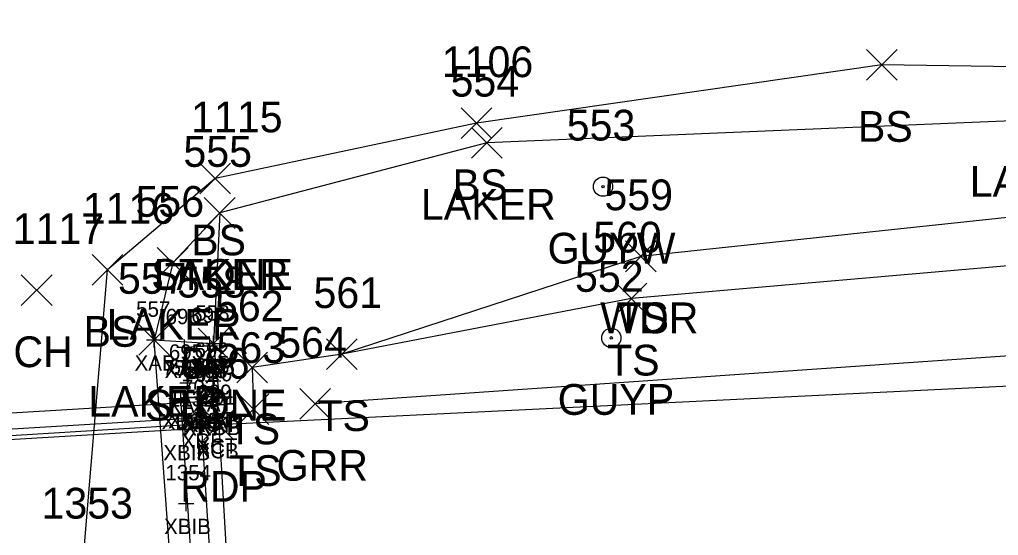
# Model space of a CAD drawing. Extents: x 1716490 to 1717645, y 888034 to 890004.
# Drawn here: x 1717164.1 to 1717227.8, y 888253.5 to 888287.1 of the extents above; entities that cross this region are included whole.
import ezdxf

# ---------------------------------------------------------------- set-up
doc = ezdxf.new("R2010")
doc.units = 0
for name, color, linetype in [('B_A', 7, 'Continuous'), ('B_I', 7, 'Continuous'), ('B_TIC', 7, 'Continuous'), ('BDC', 7, 'Continuous'), ('BF', 7, 'Continuous'), ('BR', 7, 'Continuous'), ('BSE', 7, 'Continuous'), ('BSUBM', 7, 'Continuous'), ('L_A', 7, 'Continuous'), ('L_I', 7, 'Continuous'), ('L_TIC', 7, 'Continuous'), ('LASF', 7, 'Continuous'), ('LAWA', 7, 'Continuous'), ('LAWE', 7, 'Continuous'), ('LELB', 7, 'Continuous'), ('P_A', 7, 'Continuous'), ('P_I', 7, 'Continuous'), ('P_TIC', 7, 'Continuous'), ('PET', 7, 'Continuous'), ('R_A', 7, 'Continuous'), ('R_I', 7, 'Continuous'), ('R_TIC', 7, 'Continuous'), ('RGR', 7, 'Continuous'), ('U_A', 7, 'Continuous'), ('U_I', 7, 'Continuous'), ('UPGW', 7, 'Continuous')]:
    doc.layers.add(name, color=color, linetype=linetype)

msp = doc.modelspace()

# ---------------------------------------------------------------- linework, layer by layer
at = {"layer": 'B_TIC'}
for p, q in [((1717172.863, 888266.22), (1717172.939, 888266.22)), ((1717176.717, 888265.975), (1717176.792, 888265.975)), ((1717174.834, 888265.741), (1717174.91, 888265.741)), ((1717176.473, 888265.837), (1717176.548, 888265.837)), ((1717175.018, 888263.43), (1717175.094, 888263.43)), ((1717176.687, 888263.555), (1717176.762, 888263.555)), ((1717174.599, 888262.408), (1717174.675, 888262.408)), ((1717175.062, 888262.468), (1717175.137, 888262.468)), ((1717175.803, 888262.49), (1717175.879, 888262.49)), ((1717176.593, 888262.234), (1717176.668, 888262.234)), ((1717176.593, 888262.234), (1717176.668, 888262.234)), ((1717176.726, 888262.528), (1717176.802, 888262.528)), ((1717177.084, 888262.456), (1717177.16, 888262.456)), ((1717176.001, 888261.982), (1717176.076, 888261.982)), ((1717176.979, 888262.024), (1717177.055, 888262.024)), ((1717175.884, 888261.141), (1717175.959, 888261.141)), ((1717176.881, 888260.812), (1717176.956, 888260.812)), ((1717174.882, 888260.387), (1717174.958, 888260.387)), ((1717176.87, 888260.514), (1717176.945, 888260.514)), ((1717174.931, 888255.588), (1717175.006, 888255.588))]:
    msp.add_line(p, q, dxfattribs=at)
for points in [[(1717172.86, 888265.72), (1717172.86, 888266.72)], [(1717172.36, 888266.22), (1717173.36, 888266.22)], [(1717174.831, 888265.241), (1717174.831, 888266.241)], [(1717176.213, 888265.975), (1717177.213, 888265.975)], [(1717176.469, 888265.337), (1717176.469, 888266.337)], [(1717176.713, 888265.475), (1717176.713, 888266.475)], [(1717174.331, 888265.741), (1717175.331, 888265.741)], [(1717175.969, 888265.837), (1717176.969, 888265.837)], [(1717176.683, 888263.055), (1717176.683, 888264.055)], [(1717174.515, 888263.43), (1717175.515, 888263.43)], [(1717175.015, 888262.93), (1717175.015, 888263.93)], [(1717176.183, 888263.555), (1717177.183, 888263.555)], [(1717174.596, 888261.908), (1717174.596, 888262.908)], [(1717175.058, 888261.968), (1717175.058, 888262.968)], [(1717175.8, 888261.99), (1717175.8, 888262.99)], [(1717176.589, 888261.734), (1717176.589, 888262.734)], [(1717176.589, 888261.734), (1717176.589, 888262.734)], [(1717176.723, 888262.028), (1717176.723, 888263.028)], [(1717177.081, 888261.956), (1717177.081, 888262.956)], [(1717174.096, 888262.408), (1717175.096, 888262.408)], [(1717174.558, 888262.468), (1717175.558, 888262.468)], [(1717175.3, 888262.49), (1717176.3, 888262.49)], [(1717175.997, 888261.482), (1717175.997, 888262.482)], [(1717176.089, 888262.234), (1717177.089, 888262.234)], [(1717176.089, 888262.234), (1717177.089, 888262.234)], [(1717176.223, 888262.528), (1717177.223, 888262.528)], [(1717176.581, 888262.456), (1717177.581, 888262.456)], [(1717176.976, 888261.524), (1717176.976, 888262.524)], [(1717175.497, 888261.982), (1717176.497, 888261.982)], [(1717175.88, 888260.641), (1717175.88, 888261.641)], [(1717176.476, 888262.024), (1717177.476, 888262.024)], [(1717174.879, 888259.887), (1717174.879, 888260.887)], [(1717175.38, 888261.141), (1717176.38, 888261.141)], [(1717176.377, 888260.812), (1717177.377, 888260.812)], [(1717176.866, 888260.014), (1717176.866, 888261.014)], [(1717176.877, 888260.312), (1717176.877, 888261.312)], [(1717174.379, 888260.387), (1717175.379, 888260.387)], [(1717176.366, 888260.514), (1717177.366, 888260.514)], [(1717174.927, 888255.088), (1717174.927, 888256.088)], [(1717174.427, 888255.588), (1717175.427, 888255.588)]]:
    msp.add_lwpolyline(points, dxfattribs=at)
at = {"layer": 'BDC'}
for points in [[(1717176.589, 888262.234), (1717176.877, 888260.812), (1717116.829, 888257.088), (1717056.7, 888253.344), (1716997.03, 888249.858), (1716936.998, 888246.313), (1716877.496, 888242.928), (1716877.301, 888244.49)], [(1717176.976, 888262.024), (1717176.866, 888260.514), (1717116.827, 888256.946), (1717056.83, 888253.148), (1716997.002, 888249.663), (1716937.062, 888246.095), (1716877.423, 888242.56)]]:
    msp.add_lwpolyline(points, dxfattribs=at)
at = {"layer": 'BF'}
msp.add_lwpolyline([(1717176.589, 888262.234), (1717116.538, 888258.636), (1717056.61, 888254.944), (1716996.925, 888251.433), (1716937.102, 888247.945), (1716877.301, 888244.49)], dxfattribs=at)
at = {"layer": 'BR'}
msp.add_lwpolyline([(1717175.997, 888261.982), (1717175.88, 888261.141), (1717117.062, 888257.612), (1717056.557, 888253.997), (1716997.021, 888250.409), (1716936.966, 888246.784), (1716878.141, 888243.386), (1716877.962, 888244.411)], dxfattribs=at)
at = {"layer": 'BSE'}
for points in [[(1717175.8, 888262.49), (1717174.596, 888262.408)], [(1717176.7, 888230.2), (1717174.596, 888262.408)], [(1717175.8, 888262.49), (1717177.89, 888230.3)]]:
    msp.add_lwpolyline(points, dxfattribs=at)
at = {"layer": 'BSUBM'}
for points in [[(1717172.86, 888266.22), (1717176.713, 888265.975), (1717177.081, 888262.456)], [(1717175.765, 888226.393), (1717172.86, 888266.22)], [(1717176.683, 888263.555), (1717176.723, 888262.528), (1717175.058, 888262.468), (1717175.015, 888263.43), (1717174.831, 888265.741), (1717176.469, 888265.837)], [(1717176.469, 888265.837), (1717176.683, 888263.555)]]:
    msp.add_lwpolyline(points, dxfattribs=at)
at = {"layer": 'L_TIC'}
for points in [[(1717219.203, 888283.101), (1717221.203, 888285.101)], [(1717221.203, 888283.101), (1717219.203, 888285.101)], [(1717192.827, 888279.308), (1717194.827, 888281.308)], [(1717194.827, 888279.308), (1717192.827, 888281.308)], [(1717193.5, 888278.043), (1717195.5, 888280.043)], [(1717195.5, 888278.043), (1717193.5, 888280.043)], [(1717175.82, 888275.721), (1717177.82, 888277.721)], [(1717177.82, 888275.721), (1717175.82, 888277.721)], [(1717176.118, 888273.475), (1717178.118, 888275.475)], [(1717178.118, 888273.475), (1717176.118, 888275.475)], [(1717176.118, 888273.475), (1717178.118, 888275.475)], [(1717178.118, 888273.475), (1717176.118, 888275.475)], [(1717203.517, 888270.654), (1717205.517, 888272.654)], [(1717205.517, 888270.654), (1717203.517, 888272.654)], [(1717203.517, 888270.654), (1717205.517, 888272.654)], [(1717205.517, 888270.654), (1717203.517, 888272.654)], [(1717168.821, 888269.772), (1717170.821, 888271.772)], [(1717170.821, 888269.772), (1717168.821, 888271.772)], [(1717173.059, 888270.227), (1717175.059, 888272.227)], [(1717175.059, 888270.227), (1717173.059, 888272.227)], [(1717164.209, 888268.447), (1717166.209, 888270.447)], [(1717166.209, 888268.447), (1717164.209, 888270.447)], [(1717202.911, 888267.903), (1717204.911, 888269.903)], [(1717204.911, 888267.903), (1717202.911, 888269.903)], [(1717171.86, 888265.22), (1717173.86, 888267.22)], [(1717173.86, 888265.22), (1717171.86, 888267.22)], [(1717175.713, 888264.975), (1717177.713, 888266.975)], [(1717177.713, 888264.975), (1717175.713, 888266.975)], [(1717184.063, 888264.292), (1717186.063, 888266.292)], [(1717186.063, 888264.292), (1717184.063, 888266.292)], [(1717184.063, 888264.292), (1717186.063, 888266.292)], [(1717186.063, 888264.292), (1717184.063, 888266.292)], [(1717178.223, 888263.43), (1717180.223, 888265.43)], [(1717180.223, 888263.43), (1717178.223, 888265.43)], [(1717178.323, 888260.717), (1717180.323, 888262.717)], [(1717180.323, 888260.717), (1717178.323, 888262.717)]]:
    msp.add_lwpolyline(points, dxfattribs=at)
at = {"layer": 'LASF'}
msp.add_lwpolyline([(1717177.118, 888274.475), (1717176.713, 888265.975)], dxfattribs=at)
at = {"layer": 'LAWA'}
msp.add_lwpolyline([(1717427.067, 888329.961), (1717424.149, 888313.244), (1717417.81, 888299.744), (1717405.976, 888286.015), (1717373.069, 888282.354), (1717318.582, 888277.997), (1717270.109, 888276.059), (1717231.85, 888274.551), (1717204.517, 888271.654)], dxfattribs=at)
at = {"layer": 'LAWE'}
msp.add_lwpolyline([(1717421.683, 888328.919), (1717420.886, 888312.991), (1717415.109, 888301.397), (1717401.413, 888289.205), (1717371.004, 888285.951), (1717321.686, 888282.443), (1717271.809, 888279.668), (1717230.209, 888280.531), (1717194.5, 888279.043), (1717177.118, 888274.475), (1717174.059, 888271.227), (1717172.86, 888266.22)], dxfattribs=at)
at = {"layer": 'LELB'}
for points in [[(1717397.436, 888368.91), (1717401.938, 888364.629), (1717406.066, 888347.478), (1717411.38, 888343.282), (1717409.785, 888309.959), (1717403.016, 888297.908), (1717392.211, 888290.651), (1717353.828, 888286.564), (1717306.03, 888285.644), (1717272.452, 888283.322), (1717220.203, 888284.101), (1717193.827, 888280.308), (1717176.82, 888276.721), (1717169.821, 888270.772)], [(1717414.269, 888287.03), (1717406.988, 888281.7), (1717373.99, 888277.877), (1717318.522, 888275.495), (1717269.658, 888272.606), (1717230.913, 888271.259), (1717203.911, 888268.903), (1717185.063, 888265.292), (1717179.223, 888264.43), (1717179.323, 888261.717)], [(1717204.517, 888271.654), (1717185.063, 888265.292)], [(1717168.218, 888251.599), (1717169.821, 888270.772)]]:
    msp.add_lwpolyline(points, dxfattribs=at)
at = {"layer": 'P_TIC'}
for points in [[(1717176.059, 888259.693), (1717178.059, 888261.693)], [(1717178.059, 888259.693), (1717176.059, 888261.693)]]:
    msp.add_lwpolyline(points, dxfattribs=at)
at = {"layer": 'PET'}
msp.add_lwpolyline([(1717427.273, 888275.567), (1717374.238, 888271.922), (1717317.861, 888268.58), (1717269.995, 888265.537), (1717231.181, 888263.331), (1717177.059, 888260.693), (1717177.797, 888248.053), (1717178.6, 888236.513), (1717214.025, 888237.983), (1717254.522, 888239.738), (1717289.284, 888241.313), (1717339.424, 888243.96), (1717387.667, 888246.786), (1717419.304, 888248.633), (1717429.054, 888249.533)], dxfattribs=at)
at = {"layer": 'R_TIC'}
for points in [[(1717182.335, 888261.06), (1717184.335, 888263.06)], [(1717184.335, 888261.06), (1717182.335, 888263.06)]]:
    msp.add_lwpolyline(points, dxfattribs=at)
at = {"layer": 'RGR'}
msp.add_lwpolyline([(1717414.455, 888276.435), (1717374.087, 888273.702), (1717318.257, 888270.694), (1717269.907, 888267.54), (1717230.713, 888265.344), (1717183.335, 888262.06)], dxfattribs=at)
at = {"layer": 'UPGW'}
for centre, radius in [((1717202.058, 888276.185), 0.625), ((1717202.058, 888276.185), 0.0833), ((1717202.597, 888266.347), 0.625), ((1717202.597, 888266.347), 0.0833)]:
    msp.add_circle(centre, radius, dxfattribs=at)

# ---------------------------------------------------------------- texts
at = {"layer": 'B_A'}
for s, p in [('XAB', (1717171.58, 888264.22)), ('XAT', (1717173.535, 888263.741)), ('XAT', (1717175.174, 888263.837)), ('XAB', (1717175.434, 888263.975)), ('XAT', (1717173.72, 888261.43)), ('XAT', (1717175.388, 888261.555)), ('XBS', (1717173.336, 888260.408)), ('XAT', (1717173.763, 888260.468)), ('XBS', (1717174.54, 888260.49)), ('XAT', (1717175.428, 888260.528)), ('XAB', (1717175.801, 888260.456)), ('XRF', (1717174.757, 888259.982)), ('XFAT', (1717174.845, 888260.234)), ('XCT', (1717175.31, 888260.234)), ('XCB', (1717175.712, 888260.024)), ('XRF', (1717174.64, 888259.141)), ('XCT', (1717175.598, 888258.812)), ('XCB', (1717175.603, 888258.514)), ('XBIB', (1717173.45, 888258.387)), ('XBIB', (1717173.498, 888253.588))]:
    msp.add_text(s, height=1, dxfattribs=at).set_placement(p)
at = {"layer": 'B_I'}
for s, p in [('557', (1717171.679, 888267.72)), ('558', (1717175.532, 888267.475)), ('696', (1717173.598, 888267.241)), ('697', (1717175.265, 888267.337)), ('695', (1717173.81, 888264.93)), ('692', (1717175.479, 888265.055)), ('759', (1717173.411, 888263.908)), ('694', (1717173.854, 888263.968)), ('1379', (1717174.45, 888263.99)), ('698', (1717175.384, 888263.734)), ('698', (1717175.384, 888263.734)), ('693', (1717175.518, 888264.028)), ('565', (1717175.876, 888263.956)), ('702', (1717174.777, 888263.482)), ('700', (1717175.712, 888263.524)), ('703', (1717174.66, 888262.641)), ('1132', (1717173.816, 888261.887)), ('699', (1717175.669, 888262.312)), ('701', (1717175.929, 888262.014)), ('1354', (1717173.581, 888257.088))]:
    msp.add_text(s, height=1, dxfattribs=at).set_placement(p)
at = {"layer": 'L_A'}
for s, p in [('BS', (1717218.644, 888279.101)), ('LAKER', (1717225.918, 888275.531)), ('BS', (1717192.268, 888275.308)), ('LAKER', (1717190.209, 888274.043)), ('BS', (1717175.261, 888271.721)), ('STONE', (1717172.661, 888269.475)), ('LAKER', (1717172.827, 888269.475)), ('WDR', (1717201.879, 888266.654)), ('TS', (1717202.926, 888266.654)), ('BS', (1717168.262, 888265.772)), ('LAKER', (1717169.767, 888266.227)), ('CH', (1717163.698, 888264.447)), ('TS', (1717202.32, 888263.903)), ('LAKER', (1717168.568, 888261.22)), ('STONE', (1717172.257, 888260.975)), ('TS', (1717183.472, 888260.292)), ('TS', (1717183.472, 888260.292)), ('TS', (1717177.632, 888259.43)), ('TS', (1717177.732, 888256.717))]:
    msp.add_text(s, height=2, dxfattribs=at).set_placement(p)
at = {"layer": 'L_I'}
for s, p in [('1106', (1717191.567, 888283.308)), ('554', (1717192.138, 888282.043)), ('1115', (1717175.261, 888279.721)), ('555', (1717174.756, 888277.475)), ('555', (1717174.756, 888277.475)), ('556', (1717171.641, 888274.227)), ('559', (1717202.147, 888274.654)), ('559', (1717202.147, 888274.654)), ('1116', (1717168.206, 888273.772)), ('1117', (1717163.65, 888272.447)), ('560', (1717201.415, 888271.903)), ('557', (1717170.498, 888269.22)), ('558', (1717174.351, 888268.975)), ('561', (1717183.22, 888268.292)), ('561', (1717183.22, 888268.292)), ('562', (1717176.813, 888267.43)), ('563', (1717176.913, 888264.717)), ('1353', (1717165.525, 888254.599))]:
    msp.add_text(s, height=2, dxfattribs=at).set_placement(p)
at = {"layer": 'P_A'}
msp.add_text('RDP', height=2, dxfattribs=at).set_placement((1717174.547, 888255.693))
at = {"layer": 'P_I'}
msp.add_text('566', height=2, dxfattribs=at).set_placement((1717174.594, 888263.693))
at = {"layer": 'R_A'}
msp.add_text('GRR', height=2, dxfattribs=at).set_placement((1717180.823, 888257.06))
at = {"layer": 'R_I'}
msp.add_text('564', height=2, dxfattribs=at).set_placement((1717180.925, 888265.06))
at = {"layer": 'U_A'}
for s, p in [('GUYW', (1717198.452, 888271.185)), ('GUYP', (1717199.109, 888261.347))]:
    msp.add_text(s, height=2, dxfattribs=at).set_placement(p)
at = {"layer": 'U_I'}
for s, p in [('553', (1717199.696, 888279.185)), ('552', (1717200.235, 888269.347))]:
    msp.add_text(s, height=2, dxfattribs=at).set_placement(p)

doc.saveas('drawing.dxf')
